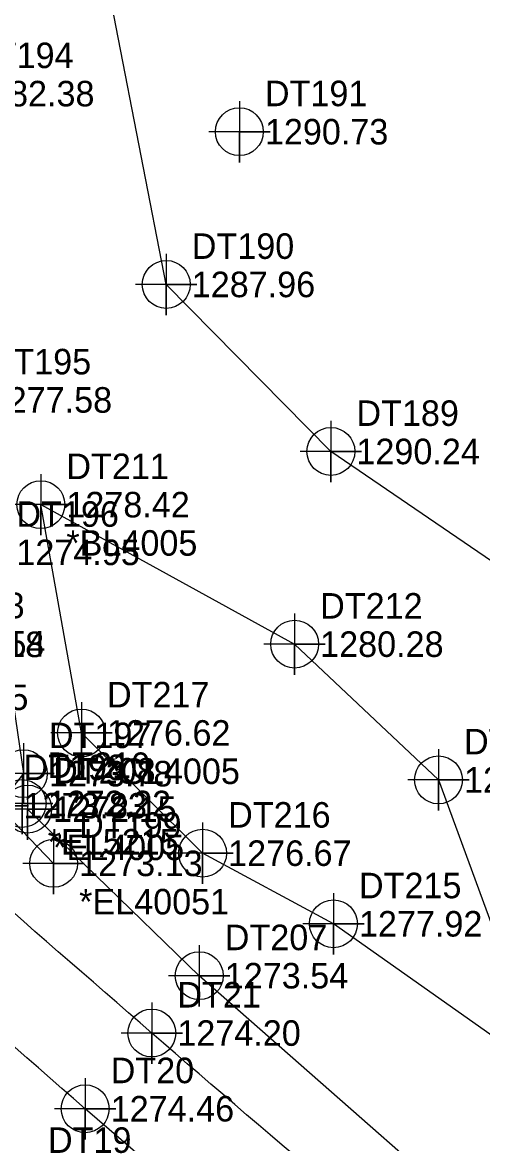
# Model space of a CAD drawing. Extents: x 1391270 to 1392151, y 960049 to 960667.
# Drawn here: x 1391696.7 to 1391741.8, y 960262.4 to 960372.1 of the extents above; entities that cross this region are included whole.
import ezdxf

# ---------------------------------------------------------------- set-up
doc = ezdxf.new("R2010")
doc.units = 0
for name, color, linetype in [('Exist DTM Breakline', 7, 'Continuous'), ('Exist DTM Breakline Cogo Comment', 7, 'Continuous'), ('Exist DTM Breakline Cogo Elevation', 7, 'Continuous'), ('Exist DTM Breakline Cogo Number', 7, 'Continuous'), ('Exist DTM Breakline Cogo Point CELL', 7, 'Continuous'), ('Exist DTM Crownline', 7, 'Continuous'), ('Exist DTM Crownline Cogo Elevation', 7, 'Continuous'), ('Exist DTM Crownline Cogo Number', 7, 'Continuous'), ('Exist DTM Crownline Cogo Point CELL', 7, 'Continuous'), ('Exist DTM Regular Point CELL', 7, 'Continuous'), ('Exist DTM Regular Point Cogo Elevation', 7, 'Continuous'), ('Exist DTM Regular Point Cogo Number', 7, 'Continuous'), ('Exist Roads EOP', 7, 'Continuous'), ('Exist Roads EOP Cogo Elevation', 7, 'Continuous'), ('Exist Roads EOP Cogo Number', 7, 'Continuous'), ('Exist Roads EOP Cogo Point CELL', 7, 'Continuous'), ('Exist Structure Minor Pipes CMP 15 Inch Cogo Comment', 7, 'Continuous'), ('Exist Structure Minor Pipes CMP 15 Inch Cogo Elevation', 7, 'Continuous'), ('Exist Structure Minor Pipes CMP 15 Inch Cogo Number', 7, 'Continuous'), ('Exist Structure Minor Pipes CMP 15 Inch Cogo Point CELL', 7, 'Continuous')]:
    doc.layers.add(name, color=color, linetype=linetype)

msp = doc.modelspace()

# ---------------------------------------------------------------- linework, layer by layer
at = {"layer": 'Exist DTM Breakline'}
for points in [[(1391689.894, 960391.525), (1391689.18, 960365.157), (1391690.906, 960335.168), (1391693.62, 960320.244), (1391696.803, 960298.575), (1391694.311, 960295.44), (1391699.762, 960289.791)], [(1391945.147, 960195.757), (1391918.09, 960213.421), (1391881.206, 960222.292), (1391849.896, 960235.631), (1391826.517, 960251.571), (1391802.004, 960268.368), (1391783.721, 960280.05), (1391763.211, 960305.363), (1391726.912, 960330.123), (1391710.789, 960346.476), (1391703.438, 960384.306)], [(1391698.511, 960324.915), (1391723.36, 960311.256), (1391737.445, 960297.964), (1391748.034, 960269.156), (1391727.16, 960283.875), (1391714.351, 960290.79), (1391702.491, 960302.562), (1391698.511, 960324.915)], [(1391918.848, 960154.955), (1391875.094, 960173.971), (1391832.683, 960194.523), (1391807.232, 960209.528), (1391789.699, 960221.943), (1391750.487, 960246.736), (1391714.022, 960278.792), (1391697.218, 960295.108)]]:
    msp.add_lwpolyline(points, dxfattribs=at)
at = {"layer": 'Exist DTM Breakline Cogo Point CELL'}
for points in [[(1391710.789, 960349.476), (1391710.789, 960343.476), (1391710.789, 960346.476), (1391713.789, 960346.476), (1391707.789, 960346.476)], [(1391726.912, 960333.123), (1391726.912, 960327.123), (1391726.912, 960330.123), (1391729.912, 960330.123), (1391723.912, 960330.123)], [(1391698.511, 960327.915), (1391698.511, 960321.915), (1391698.511, 960324.915), (1391701.511, 960324.915), (1391695.511, 960324.915)], [(1391723.36, 960314.256), (1391723.36, 960308.256), (1391723.36, 960311.256), (1391726.36, 960311.256), (1391720.36, 960311.256)], [(1391702.491, 960305.562), (1391702.491, 960299.562), (1391702.491, 960302.562), (1391705.491, 960302.562), (1391699.491, 960302.562)], [(1391696.803, 960301.575), (1391696.803, 960295.575), (1391696.803, 960298.575), (1391699.803, 960298.575), (1391693.803, 960298.575)], [(1391737.445, 960300.964), (1391737.445, 960294.964), (1391737.445, 960297.964), (1391740.445, 960297.964), (1391734.445, 960297.964)], [(1391694.311, 960298.44), (1391694.311, 960292.44), (1391694.311, 960295.44), (1391697.311, 960295.44), (1391691.311, 960295.44)], [(1391697.218, 960298.108), (1391697.218, 960292.108), (1391697.218, 960295.108), (1391700.218, 960295.108), (1391694.218, 960295.108)], [(1391714.351, 960293.79), (1391714.351, 960287.79), (1391714.351, 960290.79), (1391717.351, 960290.79), (1391711.351, 960290.79)], [(1391699.762, 960292.791), (1391699.762, 960286.791), (1391699.762, 960289.791), (1391702.762, 960289.791), (1391696.762, 960289.791)], [(1391727.16, 960286.875), (1391727.16, 960280.875), (1391727.16, 960283.875), (1391730.16, 960283.875), (1391724.16, 960283.875)], [(1391714.022, 960281.792), (1391714.022, 960275.792), (1391714.022, 960278.792), (1391717.022, 960278.792), (1391711.022, 960278.792)]]:
    msp.add_lwpolyline(points, dxfattribs=at)
for centre in [(1391710.789, 960346.476), (1391726.912, 960330.123), (1391698.511, 960324.915), (1391723.36, 960311.256), (1391702.491, 960302.562), (1391696.803, 960298.575), (1391737.445, 960297.964), (1391697.218, 960295.108), (1391714.351, 960290.79), (1391699.762, 960289.791), (1391727.16, 960283.875), (1391714.022, 960278.792)]:
    msp.add_circle(centre, 2.344, dxfattribs=at)
at = {"layer": 'Exist DTM Crownline'}
msp.add_spline([(1391912.281, 960138.966), (1391866.83, 960157.169), (1391822.661, 960179.344), (1391780.998, 960205.13), (1391740.996, 960234.086), (1391702.853, 960265.768), (1391666.471, 960297.967)], degree=3, dxfattribs=at)
at = {"layer": 'Exist DTM Crownline Cogo Point CELL'}
msp.add_lwpolyline([(1391702.853, 960268.768), (1391702.853, 960262.768), (1391702.853, 960265.768), (1391705.853, 960265.768), (1391699.853, 960265.768)], dxfattribs=at)
msp.add_circle((1391702.853, 960265.768), 2.344, dxfattribs=at)
at = {"layer": 'Exist DTM Regular Point CELL'}
msp.add_lwpolyline([(1391717.951, 960364.427), (1391717.951, 960358.427), (1391717.951, 960361.427), (1391720.951, 960361.427), (1391714.951, 960361.427)], dxfattribs=at)
msp.add_circle((1391717.951, 960361.427), 2.344, dxfattribs=at)
at = {"layer": 'Exist Roads EOP'}
for points in [[(1391915.673, 960148.156), (1391871.111, 960166.209), (1391827.705, 960187.765), (1391786.031, 960213.485), (1391746.988, 960241.829), (1391709.378, 960273.178), (1391672.886, 960305.161)], [(1391909.259, 960130.384), (1391863.262, 960148.577), (1391817.991, 960171.223), (1391775.806, 960197.201), (1391735.389, 960227.09), (1391696.713, 960258.946), (1391660.088, 960291.389)]]:
    msp.add_spline(points, degree=3, dxfattribs=at)
at = {"layer": 'Exist Roads EOP Cogo Point CELL'}
msp.add_lwpolyline([(1391709.378, 960276.178), (1391709.378, 960270.178), (1391709.378, 960273.178), (1391712.378, 960273.178), (1391706.378, 960273.178)], dxfattribs=at)
msp.add_circle((1391709.378, 960273.178), 2.344, dxfattribs=at)
at = {"layer": 'Exist Structure Minor Pipes CMP 15 Inch Cogo Point CELL'}
msp.add_lwpolyline([(1391696.681, 960298.652), (1391696.681, 960292.652), (1391696.681, 960295.652), (1391699.681, 960295.652), (1391693.681, 960295.652)], dxfattribs=at)
msp.add_circle((1391696.681, 960295.652), 2.344, dxfattribs=at)

# ---------------------------------------------------------------- texts
at = {"layer": 'Exist DTM Breakline Cogo Comment'}
for s, p in [('*BL4005', (1391701.011, 960319.915)), ('*CL4005', (1391704.991, 960297.562)), ('*EL4005', (1391699.718, 960290.108)), ('*EL40051', (1391702.262, 960284.791))]:
    msp.add_text(s, height=2.5, dxfattribs=at).set_placement(p)
at = {"layer": 'Exist DTM Breakline Cogo Elevation'}
for s, p in [('1282.38', (1391691.68, 960363.907)), ('1287.96', (1391713.289, 960345.226)), ('1277.58', (1391693.406, 960333.918)), ('1290.24', (1391729.412, 960328.873)), ('1278.42', (1391701.011, 960323.665)), ('1274.95', (1391696.12, 960318.994)), ('1274.18', (1391686.753, 960309.984)), ('1274.54', (1391686.883, 960310.042)), ('1280.28', (1391725.86, 960310.006)), ('1276.62', (1391704.991, 960301.312)), ('1273.78', (1391699.303, 960297.325)), ('1280.61', (1391739.945, 960296.714)), ('1273.83', (1391696.811, 960294.19)), ('1272.15', (1391699.718, 960293.858)), ('1276.67', (1391716.851, 960289.54)), ('1273.13', (1391702.262, 960288.541)), ('1277.92', (1391729.66, 960282.625)), ('1273.54', (1391716.522, 960277.542))]:
    msp.add_text(s, height=2.5, dxfattribs=at).set_placement(p)
at = {"layer": 'Exist DTM Breakline Cogo Number'}
for s, p in [('DT194', (1391691.68, 960367.657)), ('DT190', (1391713.289, 960348.976)), ('DT195', (1391693.406, 960337.668)), ('DT189', (1391729.412, 960332.623)), ('DT211', (1391701.011, 960327.415)), ('DT196', (1391696.12, 960322.744)), ('DT438', (1391686.883, 960313.792)), ('DT212', (1391725.86, 960313.756)), ('DT217', (1391704.991, 960305.062)), ('DT197', (1391699.303, 960301.075)), ('DT213', (1391739.945, 960300.464)), ('DT198', (1391696.811, 960297.94)), ('DT208', (1391699.718, 960297.608)), ('DT216', (1391716.851, 960293.29)), ('DT199', (1391702.262, 960292.291)), ('DT215', (1391729.66, 960286.375)), ('DT207', (1391716.522, 960281.292))]:
    msp.add_text(s, height=2.5, dxfattribs=at).set_placement(p)
at = {"layer": 'Exist DTM Crownline Cogo Elevation'}
msp.add_text('1274.46', height=2.5, dxfattribs=at).set_placement((1391705.353, 960264.518))
at = {"layer": 'Exist DTM Crownline Cogo Number'}
msp.add_text('DT20', height=2.5, dxfattribs=at).set_placement((1391705.353, 960268.268))
at = {"layer": 'Exist DTM Regular Point Cogo Elevation'}
msp.add_text('1290.73', height=2.5, dxfattribs=at).set_placement((1391720.451, 960360.177))
at = {"layer": 'Exist DTM Regular Point Cogo Number'}
msp.add_text('DT191', height=2.5, dxfattribs=at).set_placement((1391720.451, 960363.927))
at = {"layer": 'Exist Roads EOP Cogo Elevation'}
msp.add_text('1274.20', height=2.5, dxfattribs=at).set_placement((1391711.878, 960271.928))
at = {"layer": 'Exist Roads EOP Cogo Number'}
for s, p in [('DT21', (1391711.878, 960275.678)), ('DT19', (1391699.213, 960261.446))]:
    msp.add_text(s, height=2.5, dxfattribs=at).set_placement(p)
at = {"layer": 'Exist Structure Minor Pipes CMP 15 Inch Cogo Comment'}
for s, p in [('*BL5215', (1391684.469, 960304.803)), ('*EL5215', (1391699.181, 960290.652))]:
    msp.add_text(s, height=2.5, dxfattribs=at).set_placement(p)
at = {"layer": 'Exist Structure Minor Pipes CMP 15 Inch Cogo Elevation'}
msp.add_text('1272.22', height=2.5, dxfattribs=at).set_placement((1391699.181, 960294.402))
at = {"layer": 'Exist Structure Minor Pipes CMP 15 Inch Cogo Number'}
msp.add_text('DT210', height=2.5, dxfattribs=at).set_placement((1391699.181, 960298.152))

doc.saveas('drawing.dxf')
